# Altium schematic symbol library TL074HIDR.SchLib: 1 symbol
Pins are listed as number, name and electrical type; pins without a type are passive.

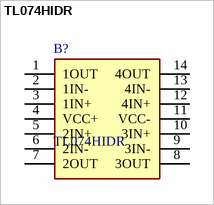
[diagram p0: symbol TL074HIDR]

## TL074HIDR
designator B?
Quad, 40-V, 5-MHz, 4-mV offset voltage, 20-V/s, In to V+ op amp with -40C to 125C operation; Manufacturer_Name: Texas Instruments; Geometry.Height: 1.75mm
footprint SOIC127P600X175-14N
pins: 1 1OUT, 2 1IN-, 3 1IN+, 4 VCC+, 5 2IN+, 6 2IN-, 7 2OUT, 8 3OUT, 9 3IN-, 10 3IN+, 11 VCC-, 12 4IN+, 13 4IN-, 14 4OUT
